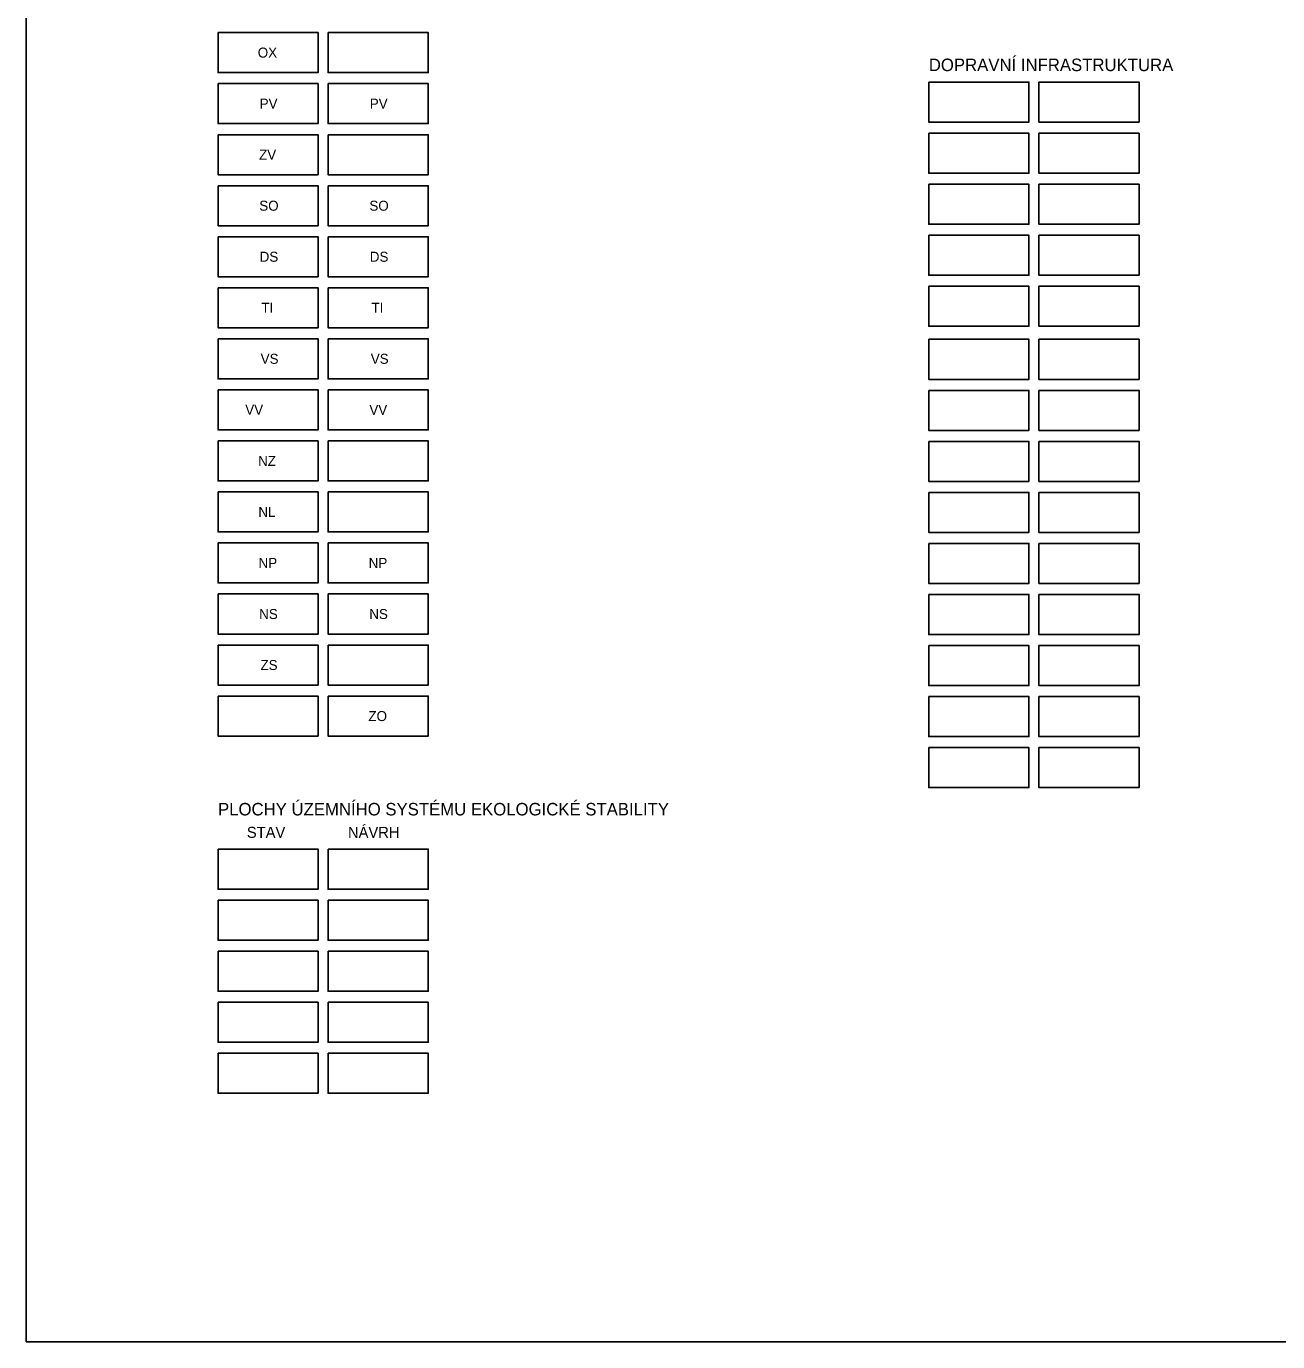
# Model space of a CAD drawing. Extents: x -547343 to -529607, y -1096298 to -1087453.
# Drawn here: x -537594 to -536344, y -1096268 to -1094954 of the extents above; entities that cross this region are included whole.
import ezdxf

# ---------------------------------------------------------------- set-up
doc = ezdxf.new("R2010")
doc.units = 0
for name, color, linetype in [('Vrstva 1', 7, 'Continuous'), ('Vrstva 10', 7, 'Continuous'), ('Vrstva 11', 7, 'Continuous')]:
    doc.layers.add(name, color=color, linetype=linetype)

msp = doc.modelspace()

# ---------------------------------------------------------------- linework, layer by layer
at = {"layer": 'Vrstva 1'}
for points in [[(-537594.4, -1093636.1), (-535094.4, -1093636.1), (-535094.4, -1096268.5), (-537594.4, -1096268.5)], [(-537402.9, -1094960.3), (-537302.9, -1094960.3), (-537302.9, -1095000.3), (-537402.9, -1095000.3)], [(-537292.9, -1094960.3), (-537192.9, -1094960.3), (-537192.9, -1095000.3), (-537292.9, -1095000.3)], [(-537402.9, -1095011.3), (-537302.9, -1095011.3), (-537302.9, -1095051.3), (-537402.9, -1095051.3)], [(-537292.9, -1095011.3), (-537192.9, -1095011.3), (-537192.9, -1095051.3), (-537292.9, -1095051.3)], [(-536692.9, -1095009.8), (-536592.9, -1095009.8), (-536592.9, -1095049.8), (-536692.9, -1095049.8)], [(-536582.9, -1095009.8), (-536482.9, -1095009.8), (-536482.9, -1095049.8), (-536582.9, -1095049.8)], [(-537402.9, -1095062.3), (-537302.9, -1095062.3), (-537302.9, -1095102.3), (-537402.9, -1095102.3)], [(-537292.9, -1095062.3), (-537192.9, -1095062.3), (-537192.9, -1095102.3), (-537292.9, -1095102.3)], [(-536692.9, -1095060.8), (-536592.9, -1095060.8), (-536592.9, -1095100.8), (-536692.9, -1095100.8)], [(-536582.9, -1095060.8), (-536482.9, -1095060.8), (-536482.9, -1095100.8), (-536582.9, -1095100.8)], [(-537402.9, -1095113.3), (-537302.9, -1095113.3), (-537302.9, -1095153.3), (-537402.9, -1095153.3)], [(-537292.9, -1095113.3), (-537192.9, -1095113.3), (-537192.9, -1095153.3), (-537292.9, -1095153.3)], [(-536692.9, -1095111.8), (-536592.9, -1095111.8), (-536592.9, -1095151.8), (-536692.9, -1095151.8)], [(-536582.9, -1095111.8), (-536482.9, -1095111.8), (-536482.9, -1095151.8), (-536582.9, -1095151.8)], [(-536692.9, -1095162.8), (-536592.9, -1095162.8), (-536592.9, -1095202.8), (-536692.9, -1095202.8)], [(-536582.9, -1095162.8), (-536482.9, -1095162.8), (-536482.9, -1095202.8), (-536582.9, -1095202.8)], [(-537402.9, -1095164.3), (-537302.9, -1095164.3), (-537302.9, -1095204.3), (-537402.9, -1095204.3)], [(-537292.9, -1095164.3), (-537192.9, -1095164.3), (-537192.9, -1095204.3), (-537292.9, -1095204.3)], [(-537402.9, -1095215.3), (-537302.9, -1095215.3), (-537302.9, -1095255.3), (-537402.9, -1095255.3)], [(-537292.9, -1095215.3), (-537192.9, -1095215.3), (-537192.9, -1095255.3), (-537292.9, -1095255.3)], [(-536692.9, -1095213.8), (-536592.9, -1095213.8), (-536592.9, -1095253.8), (-536692.9, -1095253.8)], [(-536582.9, -1095213.8), (-536482.9, -1095213.8), (-536482.9, -1095253.8), (-536582.9, -1095253.8)], [(-537402.9, -1095266.3), (-537302.9, -1095266.3), (-537302.9, -1095306.3), (-537402.9, -1095306.3)], [(-537292.9, -1095266.3), (-537192.9, -1095266.3), (-537192.9, -1095306.3), (-537292.9, -1095306.3)], [(-536692.9, -1095266.8), (-536592.9, -1095266.8), (-536592.9, -1095306.8), (-536692.9, -1095306.8)], [(-536582.9, -1095266.8), (-536482.9, -1095266.8), (-536482.9, -1095306.8), (-536582.9, -1095306.8)], [(-537402.9, -1095317.3), (-537302.9, -1095317.3), (-537302.9, -1095357.3), (-537402.9, -1095357.3)], [(-537292.9, -1095317.3), (-537192.9, -1095317.3), (-537192.9, -1095357.3), (-537292.9, -1095357.3)], [(-536692.9, -1095317.8), (-536592.9, -1095317.8), (-536592.9, -1095357.8), (-536692.9, -1095357.8)], [(-536582.9, -1095317.8), (-536482.9, -1095317.8), (-536482.9, -1095357.8), (-536582.9, -1095357.8)], [(-537402.9, -1095368.3), (-537302.9, -1095368.3), (-537302.9, -1095408.3), (-537402.9, -1095408.3)], [(-537292.9, -1095368.3), (-537192.9, -1095368.3), (-537192.9, -1095408.3), (-537292.9, -1095408.3)], [(-536692.9, -1095368.8), (-536592.9, -1095368.8), (-536592.9, -1095408.8), (-536692.9, -1095408.8)], [(-536582.9, -1095368.8), (-536482.9, -1095368.8), (-536482.9, -1095408.8), (-536582.9, -1095408.8)], [(-537402.9, -1095419.3), (-537302.9, -1095419.3), (-537302.9, -1095459.3), (-537402.9, -1095459.3)], [(-537292.9, -1095419.3), (-537192.9, -1095419.3), (-537192.9, -1095459.3), (-537292.9, -1095459.3)], [(-536692.9, -1095419.8), (-536592.9, -1095419.8), (-536592.9, -1095459.8), (-536692.9, -1095459.8)], [(-536582.9, -1095419.8), (-536482.9, -1095419.8), (-536482.9, -1095459.8), (-536582.9, -1095459.8)], [(-537402.9, -1095470.3), (-537302.9, -1095470.3), (-537302.9, -1095510.3), (-537402.9, -1095510.3)], [(-537292.9, -1095470.3), (-537192.9, -1095470.3), (-537192.9, -1095510.3), (-537292.9, -1095510.3)], [(-536692.9, -1095470.8), (-536592.9, -1095470.8), (-536592.9, -1095510.8), (-536692.9, -1095510.8)], [(-536582.9, -1095470.8), (-536482.9, -1095470.8), (-536482.9, -1095510.8), (-536582.9, -1095510.8)], [(-537402.9, -1095521.3), (-537302.9, -1095521.3), (-537302.9, -1095561.3), (-537402.9, -1095561.3)], [(-537292.9, -1095521.3), (-537192.9, -1095521.3), (-537192.9, -1095561.3), (-537292.9, -1095561.3)], [(-536692.9, -1095521.8), (-536592.9, -1095521.8), (-536592.9, -1095561.8), (-536692.9, -1095561.8)], [(-536582.9, -1095521.8), (-536482.9, -1095521.8), (-536482.9, -1095561.8), (-536582.9, -1095561.8)], [(-537402.9, -1095572.3), (-537302.9, -1095572.3), (-537302.9, -1095612.3), (-537402.9, -1095612.3)], [(-537292.9, -1095572.3), (-537192.9, -1095572.3), (-537192.9, -1095612.3), (-537292.9, -1095612.3)], [(-536692.9, -1095572.8), (-536592.9, -1095572.8), (-536592.9, -1095612.8), (-536692.9, -1095612.8)], [(-536582.9, -1095572.8), (-536482.9, -1095572.8), (-536482.9, -1095612.8), (-536582.9, -1095612.8)], [(-537402.9, -1095623.3), (-537302.9, -1095623.3), (-537302.9, -1095663.3), (-537402.9, -1095663.3)], [(-537292.9, -1095623.3), (-537192.9, -1095623.3), (-537192.9, -1095663.3), (-537292.9, -1095663.3)], [(-536692.9, -1095623.8), (-536592.9, -1095623.8), (-536592.9, -1095663.8), (-536692.9, -1095663.8)], [(-536582.9, -1095623.8), (-536482.9, -1095623.8), (-536482.9, -1095663.8), (-536582.9, -1095663.8)], [(-536692.9, -1095674.8), (-536592.9, -1095674.8), (-536592.9, -1095714.8), (-536692.9, -1095714.8)], [(-536582.9, -1095674.8), (-536482.9, -1095674.8), (-536482.9, -1095714.8), (-536582.9, -1095714.8)], [(-537402.9, -1095776.3), (-537302.9, -1095776.3), (-537302.9, -1095816.3), (-537402.9, -1095816.3)], [(-537292.9, -1095776.3), (-537192.9, -1095776.3), (-537192.9, -1095816.3), (-537292.9, -1095816.3)], [(-537402.9, -1095827.3), (-537302.9, -1095827.3), (-537302.9, -1095867.3), (-537402.9, -1095867.3)], [(-537292.9, -1095827.3), (-537192.9, -1095827.3), (-537192.9, -1095867.3), (-537292.9, -1095867.3)], [(-537402.9, -1095878.3), (-537302.9, -1095878.3), (-537302.9, -1095918.3), (-537402.9, -1095918.3)], [(-537292.9, -1095878.3), (-537192.9, -1095878.3), (-537192.9, -1095918.3), (-537292.9, -1095918.3)], [(-537402.9, -1095929.3), (-537302.9, -1095929.3), (-537302.9, -1095969.3), (-537402.9, -1095969.3)], [(-537292.9, -1095929.3), (-537192.9, -1095929.3), (-537192.9, -1095969.3), (-537292.9, -1095969.3)], [(-537402.9, -1095980.3), (-537302.9, -1095980.3), (-537302.9, -1096020.3), (-537402.9, -1096020.3)], [(-537402.9, -1095980.3), (-537302.9, -1095980.3), (-537302.9, -1096020.3), (-537402.9, -1096020.3)], [(-537292.9, -1095980.3), (-537192.9, -1095980.3), (-537192.9, -1096020.3), (-537292.9, -1096020.3)], [(-537292.9, -1095980.3), (-537192.9, -1095980.3), (-537192.9, -1096020.3), (-537292.9, -1096020.3)]]:
    msp.add_lwpolyline(points, close=True, dxfattribs=at)

# ---------------------------------------------------------------- texts
for s, height, p in [('DOPRAVNÍ INFRASTRUKTURA', 12.5, (-536692.9, -1094998.8)), ('PLOCHY ÚZEMNÍHO SYSTÉMU EKOLOGICKÉ STABILITY', 12.5, (-537402.9, -1095742.6)), ('STAV', 11, (-537374.1, -1095765)), ('NÁVRH', 11, (-537273.1, -1095765))]:
    msp.add_text(s, height=height, dxfattribs=at).set_placement(p)
at = {"layer": 'Vrstva 10'}
for s, p in [('OX', (-537363.2, -1094985.3)), ('PV', (-537361.3, -1095036.3)), ('ZV', (-537361.9, -1095087.3)), ('SO', (-537361.7, -1095138.3)), ('DS', (-537361.3, -1095189.3)), ('TI', (-537359.6, -1095240.3)), ('VS', (-537360.3, -1095291.3)), ('VV', (-537375.7, -1095342.2)), ('NZ', (-537362.9, -1095393.3)), ('NL', (-537362.6, -1095444.3)), ('NP', (-537362.4, -1095495.3)), ('NS', (-537361.8, -1095546.3)), ('ZS', (-537360.5, -1095597.3))]:
    msp.add_text(s, height=10, dxfattribs=at).set_placement(p)
at = {"layer": 'Vrstva 11'}
for s, p in [('PV', (-537251.3, -1095036.3)), ('SO', (-537251.7, -1095138.3)), ('DS', (-537251.3, -1095189.3)), ('TI', (-537249.6, -1095240.3)), ('VS', (-537250.3, -1095291.3)), ('VV', (-537251.7, -1095342.3)), ('NP', (-537252.4, -1095495.3)), ('NS', (-537251.8, -1095546.3)), ('ZO', (-537252.7, -1095648.3))]:
    msp.add_text(s, height=10, dxfattribs=at).set_placement(p)

doc.saveas('drawing.dxf')
